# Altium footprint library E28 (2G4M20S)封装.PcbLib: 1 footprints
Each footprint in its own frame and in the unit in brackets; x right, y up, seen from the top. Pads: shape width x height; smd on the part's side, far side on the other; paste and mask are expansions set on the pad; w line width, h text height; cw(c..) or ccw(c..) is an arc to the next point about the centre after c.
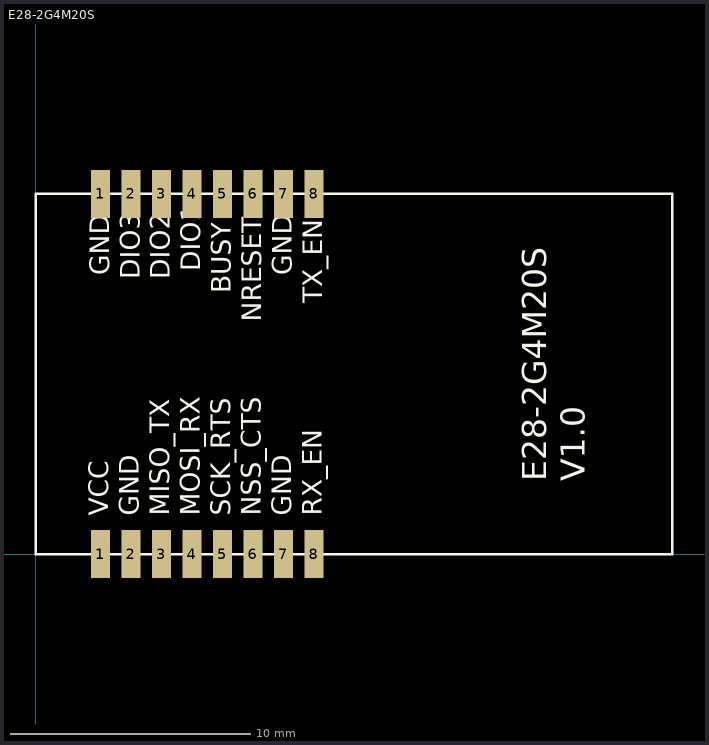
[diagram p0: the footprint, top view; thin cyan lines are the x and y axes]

## E28-2G4M20S [mm]
pads (16):
  rect 0.8x2 smd: 1(2.69,0) 1(2.69,15) 2(3.96,0) 2(3.96,15) 3(5.23,0) 3(5.23,15) 4(6.5,0) 4(6.5,15) 5(7.77,0) 5(7.77,15) 6(9.04,0) 6(9.04,15) 7(10.31,0) 7(10.31,15) 8(11.58,0) 8(11.58,15)
Top Overlay:
  lines w0.1: 0,0 0,15 26.5,15 26.5,0 0,0
  text "V1.0" at 22.85,3.03 h1
  text "TX_EN" at 11.93,10.437 h0.8
  text "RX_EN" at 11.9,1.6 h0.8
  text "VCC" at 3.02,1.6 h0.8
  text "GND" at 4.289,1.6 h0.8
  text "MISO_TX" at 5.557,1.6 h0.8
  text "MOSI_RX" at 6.826,1.6 h0.8
  text "SCK_RTS" at 8.094,1.6 h0.8
  text "NSS_CTS" at 9.363,1.6 h0.8
  text "GND" at 10.631,1.6 h0.8
  text "GND" at 10.661,11.61 h0.8
  text "NRESET" at 9.393,9.682 h0.8
  text "BUSY" at 8.124,10.863 h0.8
  text "DIO1" at 6.856,11.785 h0.8
  text "DIO2" at 5.587,11.442 h0.8
  text "DIO3" at 4.319,11.442 h0.8
  text "GND" at 3.05,11.61 h0.8
  text "E28-2G4M20S" at 21.26,3.03 h1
